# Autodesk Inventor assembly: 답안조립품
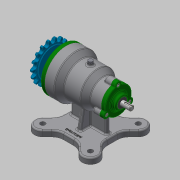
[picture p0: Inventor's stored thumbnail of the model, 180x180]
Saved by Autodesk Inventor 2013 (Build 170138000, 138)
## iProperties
Created: 2017-03
Part Number: 답안조립품
Document SubType Name: Assembly
Designer: Administrator
Author: Administrator
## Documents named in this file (14)
- C:\Users\Administrator\Desktop\470307V1023\답안조립품.iam
- C:\Users\Administrator\Desktop\470307V1023\답안본체.ipt
- C:\Users\Administrator\Desktop\470307V1023\뒤커버.ipt
- C:\Users\Administrator\Desktop\470307V1023\베어링-6200.ipt
- C:\Users\Administrator\Desktop\470307V1023\베어링-6203.ipt
- C:\Users\Administrator\Desktop\470307V1023\볼트 M4 x 12.ipt
- C:\Users\Administrator\Desktop\470307V1023\볼트 M5 x 10.ipt
- 볼트 M5 x 10.ipt
- C:\Users\Administrator\Desktop\470307V1023\스프로킷.ipt
- C:\Users\Administrator\Desktop\470307V1023\앞커버.ipt
- C:\Users\Administrator\Desktop\470307V1023\오일 실 10 20 7.ipt
- C:\Users\Administrator\Desktop\470307V1023\오일 실 17 30 8.ipt
- C:\Users\Administrator\Desktop\470307V1023\축.ipt
- C:\Users\Administrator\Desktop\470307V1023\키5x5.ipt
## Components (9 placed, 1 different names)
1. ISO 4762 M4 x 12:1
2. ISO 4762 M4 x 12:2
3. ISO 4762 M4 x 12:3
4. ISO 4762 M4 x 12:4
5. ISO 4762 M4 x 12:5
6. ISO 4762 M4 x 12:6
7. ISO 4762 M4 x 12:7
8. ISO 4762 M4 x 12:8
9. ISO 4762 M4 x 12:9
